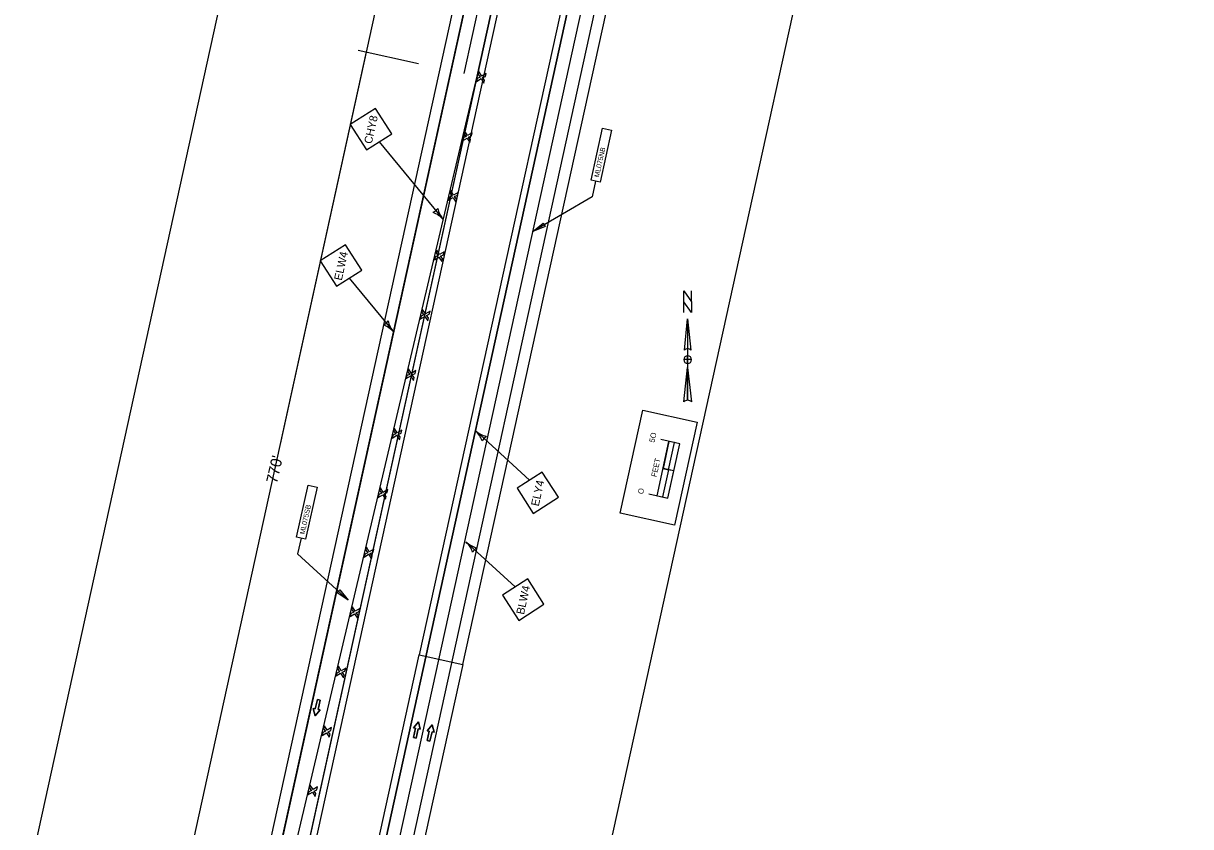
# Model space of a CAD drawing. Extents: x 14104283 to 14120882, y 8635219 to 8671666.
# Drawn here: x 14108027 to 14109077, y 8641619 to 8642342 of the extents above; entities that cross this region are included whole.
import ezdxf

# ---------------------------------------------------------------- set-up
doc = ezdxf.new("R2010")
doc.units = 0
for name, color, linetype in [('Cell', 7, 'Continuous'), ('dsnCellsNorthArrow', 7, 'Continuous'), ('dsnCellsScaleBlock', 7, 'Continuous'), ('dsnNonPlotable', 7, 'Continuous'), ('dsnPaintExistingEdgeLineRightWhite', 7, 'Continuous'), ('dsnPaintPlaceBrokenLineWhite', 7, 'Continuous'), ('dsnPaintPlaceEdgeLineLeftYellow', 7, 'Continuous'), ('dsnPaintPlaceEdgeLineRightWhite', 7, 'Continuous'), ('dsnPaintRemoveDoubleCenterLineYellow', 7, 'Continuous'), ('dsnShadingPaved', 7, 'Continuous'), ('dsnStdLabel', 7, 'Continuous'), ('dsnStgShadingPrevPav', 7, 'Continuous'), ('dsnTapePlaceChannelizingLaneYellow', 7, 'Continuous'), ('Text', 7, 'Continuous')]:
    doc.layers.add(name, color=color, linetype=linetype)

msp = doc.modelspace()

# ---------------------------------------------------------------- linework, layer by layer
at = {"layer": 'Cell'}
for p, q in [((14108436.6, 8642298.3), (14108435.9, 8642295.6)), ((14108439.1, 8642294.2), (14108436.6, 8642298.3)), ((14108443.1, 8642296.7), (14108439.1, 8642294.2)), ((14108442.5, 8642294), (14108443.1, 8642296.7)), ((14108435.1, 8642292.2), (14108434.5, 8642289.5)), ((14108434.5, 8642289.5), (14108438.5, 8642292)), ((14108437.7, 8642293.4), (14108435.1, 8642292.2)), ((14108435.9, 8642295.6), (14108437.7, 8642293.4)), ((14108438.5, 8642292), (14108441, 8642288)), ((14108439.9, 8642292.9), (14108442.5, 8642294)), ((14108441.7, 8642290.6), (14108439.9, 8642292.9)), ((14108441, 8642288), (14108441.7, 8642290.6)), ((14108423.9, 8642244.8), (14108423.3, 8642242.1)), ((14108426.4, 8642240.7), (14108423.9, 8642244.8)), ((14108422.5, 8642238.7), (14108421.8, 8642236)), ((14108421.8, 8642236), (14108425.9, 8642238.5)), ((14108425.1, 8642239.9), (14108422.5, 8642238.7)), ((14108423.3, 8642242.1), (14108425.1, 8642239.9)), ((14108425.9, 8642238.5), (14108428.4, 8642234.4)), ((14108430.5, 8642243.2), (14108426.4, 8642240.7)), ((14108427.3, 8642239.3), (14108429.9, 8642240.5)), ((14108429, 8642237.1), (14108427.3, 8642239.3)), ((14108428.4, 8642234.4), (14108429, 8642237.1)), ((14108429.9, 8642240.5), (14108430.5, 8642243.2)), ((14108411.3, 8642191.2), (14108410.7, 8642188.6)), ((14108413.8, 8642187.2), (14108411.3, 8642191.2)), ((14108409.8, 8642185.2), (14108409.2, 8642182.5)), ((14108409.2, 8642182.5), (14108413.3, 8642185)), ((14108412.4, 8642186.3), (14108409.8, 8642185.2)), ((14108410.7, 8642188.6), (14108412.4, 8642186.3)), ((14108413.3, 8642185), (14108415.7, 8642180.9)), ((14108417.9, 8642189.6), (14108413.8, 8642187.2)), ((14108414.6, 8642185.8), (14108417.2, 8642187)), ((14108416.4, 8642183.6), (14108414.6, 8642185.8)), ((14108415.7, 8642180.9), (14108416.4, 8642183.6)), ((14108417.2, 8642187), (14108417.9, 8642189.6)), ((14108397.2, 8642131.6), (14108396.5, 8642129)), ((14108396.5, 8642129), (14108400.6, 8642131.4)), ((14108399.8, 8642132.8), (14108397.2, 8642131.6)), ((14108398.7, 8642137.7), (14108398, 8642135)), ((14108398, 8642135), (14108399.8, 8642132.8)), ((14108401.2, 8642133.6), (14108398.7, 8642137.7)), ((14108400.6, 8642131.4), (14108403.1, 8642127.4)), ((14108405.2, 8642136.1), (14108401.2, 8642133.6)), ((14108402, 8642132.3), (14108404.6, 8642133.4)), ((14108403.8, 8642130), (14108402, 8642132.3)), ((14108403.1, 8642127.4), (14108403.8, 8642130)), ((14108404.6, 8642133.4), (14108405.2, 8642136.1)), ((14108384.6, 8642078.1), (14108383.9, 8642075.4)), ((14108383.9, 8642075.4), (14108388, 8642077.9)), ((14108387.2, 8642079.3), (14108384.6, 8642078.1)), ((14108386, 8642084.2), (14108385.4, 8642081.5)), ((14108385.4, 8642081.5), (14108387.2, 8642079.3)), ((14108388.5, 8642080.1), (14108386, 8642084.2)), ((14108388, 8642077.9), (14108390.5, 8642073.8)), ((14108392.6, 8642082.6), (14108388.5, 8642080.1)), ((14108389.3, 8642078.7), (14108391.9, 8642079.9)), ((14108391.1, 8642076.5), (14108389.3, 8642078.7)), ((14108390.5, 8642073.8), (14108391.1, 8642076.5)), ((14108391.9, 8642079.9), (14108392.6, 8642082.6)), ((14108371.9, 8642024.6), (14108371.3, 8642021.9)), ((14108371.3, 8642021.9), (14108375.4, 8642024.4)), ((14108374.5, 8642025.7), (14108371.9, 8642024.6)), ((14108373.4, 8642030.6), (14108372.7, 8642028)), ((14108372.7, 8642028), (14108374.5, 8642025.7)), ((14108375.9, 8642026.6), (14108373.4, 8642030.6)), ((14108375.4, 8642024.4), (14108377.8, 8642020.3)), ((14108380, 8642029.1), (14108375.9, 8642026.6)), ((14108376.7, 8642025.2), (14108379.3, 8642026.4)), ((14108378.5, 8642023), (14108376.7, 8642025.2)), ((14108377.8, 8642020.3), (14108378.5, 8642023)), ((14108379.3, 8642026.4), (14108380, 8642029.1)), ((14108359.3, 8641971), (14108358.6, 8641968.4)), ((14108358.6, 8641968.4), (14108362.7, 8641970.9)), ((14108361.9, 8641972.2), (14108359.3, 8641971)), ((14108360.8, 8641977.1), (14108360.1, 8641974.4)), ((14108360.1, 8641974.4), (14108361.9, 8641972.2)), ((14108363.2, 8641973), (14108360.8, 8641977.1)), ((14108362.7, 8641970.9), (14108365.2, 8641966.8)), ((14108367.3, 8641975.5), (14108363.2, 8641973)), ((14108364.1, 8641971.7), (14108366.7, 8641972.9)), ((14108365.8, 8641969.5), (14108364.1, 8641971.7)), ((14108366.7, 8641972.9), (14108367.3, 8641975.5)), ((14108365.2, 8641966.8), (14108365.8, 8641969.5)), ((14108349.2, 8641918.7), (14108346.7, 8641917.5)), ((14108348.1, 8641923.6), (14108347.5, 8641920.9)), ((14108347.5, 8641920.9), (14108349.2, 8641918.7)), ((14108350.6, 8641919.5), (14108348.1, 8641923.6)), ((14108354.7, 8641922), (14108350.6, 8641919.5)), ((14108351.4, 8641918.2), (14108354, 8641919.3)), ((14108353.2, 8641915.9), (14108351.4, 8641918.2)), ((14108354, 8641919.3), (14108354.7, 8641922)), ((14108346.7, 8641917.5), (14108346, 8641914.8)), ((14108346, 8641914.8), (14108350.1, 8641917.3)), ((14108350.1, 8641917.3), (14108352.6, 8641913.3)), ((14108352.6, 8641913.3), (14108353.2, 8641915.9)), ((14108335.5, 8641870.1), (14108334.8, 8641867.4)), ((14108334.8, 8641867.4), (14108336.6, 8641865.2)), ((14108338, 8641866), (14108335.5, 8641870.1)), ((14108342, 8641868.5), (14108338, 8641866)), ((14108338.8, 8641864.6), (14108341.4, 8641865.8)), ((14108341.4, 8641865.8), (14108342, 8641868.5)), ((14108334, 8641864), (14108333.4, 8641861.3)), ((14108333.4, 8641861.3), (14108337.4, 8641863.8)), ((14108336.6, 8641865.2), (14108334, 8641864)), ((14108337.4, 8641863.8), (14108339.9, 8641859.7)), ((14108340.6, 8641862.4), (14108338.8, 8641864.6)), ((14108339.9, 8641859.7), (14108340.6, 8641862.4)), ((14108322.8, 8641816.5), (14108322.2, 8641813.9)), ((14108322.2, 8641813.9), (14108324, 8641811.6)), ((14108325.3, 8641812.5), (14108322.8, 8641816.5)), ((14108329.4, 8641814.9), (14108325.3, 8641812.5)), ((14108328.8, 8641812.3), (14108329.4, 8641814.9)), ((14108321.4, 8641810.5), (14108320.7, 8641807.8)), ((14108320.7, 8641807.8), (14108324.8, 8641810.3)), ((14108324, 8641811.6), (14108321.4, 8641810.5)), ((14108324.8, 8641810.3), (14108327.3, 8641806.2)), ((14108326.2, 8641811.1), (14108328.8, 8641812.3)), ((14108327.9, 8641808.9), (14108326.2, 8641811.1)), ((14108327.3, 8641806.2), (14108327.9, 8641808.9)), ((14108310.2, 8641763), (14108309.6, 8641760.3)), ((14108312.7, 8641758.9), (14108310.2, 8641763)), ((14108316.8, 8641761.4), (14108312.7, 8641758.9)), ((14108316.1, 8641758.7), (14108316.8, 8641761.4)), ((14108308.7, 8641756.9), (14108308.1, 8641754.3)), ((14108308.1, 8641754.3), (14108312.2, 8641756.7)), ((14108311.3, 8641758.1), (14108308.7, 8641756.9)), ((14108309.6, 8641760.3), (14108311.3, 8641758.1)), ((14108312.2, 8641756.7), (14108314.7, 8641752.7)), ((14108313.5, 8641757.6), (14108316.1, 8641758.7)), ((14108315.3, 8641755.3), (14108313.5, 8641757.6)), ((14108314.7, 8641752.7), (14108315.3, 8641755.3)), ((14108297.6, 8641709.5), (14108296.9, 8641706.8)), ((14108300.1, 8641705.4), (14108297.6, 8641709.5)), ((14108296.1, 8641703.4), (14108295.5, 8641700.7)), ((14108295.5, 8641700.7), (14108299.5, 8641703.2)), ((14108298.7, 8641704.6), (14108296.1, 8641703.4)), ((14108296.9, 8641706.8), (14108298.7, 8641704.6)), ((14108299.5, 8641703.2), (14108302, 8641699.1)), ((14108304.1, 8641707.9), (14108300.1, 8641705.4)), ((14108300.9, 8641704), (14108303.5, 8641705.2)), ((14108302.7, 8641701.8), (14108300.9, 8641704)), ((14108302, 8641699.1), (14108302.7, 8641701.8)), ((14108303.5, 8641705.2), (14108304.1, 8641707.9)), ((14108284.9, 8641655.9), (14108284.3, 8641653.3)), ((14108287.4, 8641651.9), (14108284.9, 8641655.9)), ((14108283.5, 8641649.9), (14108282.8, 8641647.2)), ((14108282.8, 8641647.2), (14108286.9, 8641649.7)), ((14108286.1, 8641651), (14108283.5, 8641649.9)), ((14108284.3, 8641653.3), (14108286.1, 8641651)), ((14108286.9, 8641649.7), (14108289.4, 8641645.6)), ((14108291.5, 8641654.4), (14108287.4, 8641651.9)), ((14108288.3, 8641650.5), (14108290.9, 8641651.7)), ((14108290, 8641648.3), (14108288.3, 8641650.5)), ((14108289.4, 8641645.6), (14108290, 8641648.3)), ((14108290.9, 8641651.7), (14108291.5, 8641654.4))]:
    msp.add_line(p, q, dxfattribs=at)
for points in [[(14108291.3, 8641733.2), (14108293.7, 8641732.6), (14108291.9, 8641724.1), (14108293.7, 8641723.7), (14108289.3, 8641718.3), (14108287.6, 8641725), (14108289.4, 8641724.6)], [(14108380.2, 8641698.2), (14108377.7, 8641698.8), (14108379.6, 8641707.3), (14108377.8, 8641707.7), (14108382.2, 8641713.1), (14108383.9, 8641706.4), (14108382.1, 8641706.8)], [(14108392.5, 8641695.5), (14108390.1, 8641696.1), (14108391.9, 8641704.6), (14108390.1, 8641705), (14108394.5, 8641710.4), (14108396.2, 8641703.7), (14108394.4, 8641704.1)]]:
    msp.add_lwpolyline(points, close=True, dxfattribs=at)
for points in [[(14108289.4, 8641724.6), (14108287.6, 8641725), (14108289.3, 8641718.3), (14108293.7, 8641723.7), (14108291.9, 8641724.1), (14108293.7, 8641732.6), (14108291.3, 8641733.2), (14108289.4, 8641724.6)], [(14108382.1, 8641706.8), (14108383.9, 8641706.4), (14108382.2, 8641713.1), (14108377.8, 8641707.7), (14108379.6, 8641707.3), (14108377.7, 8641698.8), (14108380.2, 8641698.2), (14108382.1, 8641706.8)], [(14108394.4, 8641704.1), (14108396.2, 8641703.7), (14108394.5, 8641710.4), (14108390.1, 8641705), (14108391.9, 8641704.6), (14108390.1, 8641696.1), (14108392.5, 8641695.5), (14108394.4, 8641704.1)]]:
    msp.add_lwpolyline(points, dxfattribs=at)
at = {"layer": 'dsnCellsNorthArrow'}
for p, q in [((14108624.4, 8642075.6), (14108627.2, 8642047.4)), ((14108624.4, 8642075.6), (14108624.4, 8642002.4)), ((14108621.6, 8642047.4), (14108621.6, 8642047.4)), ((14108621.7, 8642047.7), (14108622.2, 8642048.3)), ((14108624.4, 8642035.5), (14108624.4, 8642035.5)), ((14108620.9, 8642001), (14108624.4, 8642032))]:
    msp.add_line(p, q, dxfattribs=at)
msp.add_lwpolyline([(14108627.9, 8642081.3), (14108620.9, 8642091.1), (14108620.9, 8642101), (14108627.9, 8642091.1)], close=True, dxfattribs=at)
for points in [[(14108620.9, 8642081.3), (14108620.9, 8642101), (14108627.9, 8642091.1), (14108627.9, 8642101)], [(14108621.6, 8642047.4), (14108624.4, 8642075.6), (14108624.4, 8642048.9)], [(14108624.4, 8642035.5), (14108624.4, 8642039), (14108620.9, 8642039)], [(14108627.9, 8642039), (14108624.4, 8642039), (14108624.4, 8642042.5)], [(14108624.4, 8642002.4), (14108624.4, 8642032), (14108627.9, 8642001)]]:
    msp.add_lwpolyline(points, dxfattribs=at)
for centre, radius, start, end in [((14108624.4, 8642045.3), 3.52, 90.0204, 143.1257), ((14108624.4, 8642045.3), 3.52, 36.8481, 90.0218), ((14108624.4, 8642039), 3.52, 90, 180), ((14108624.4, 8642039), 3.52, 180, 270), ((14108624.4, 8642039), 3.52, 0, 90), ((14108624.4, 8642039), 3.52, 270, 360), ((14108624.4, 8641997.3), 5.1, 89.9894, 133.619), ((14108624.4, 8641997.3), 5.11, 46.4021, 90.0006)]:
    msp.add_arc(centre, radius, start, end, dxfattribs=at)
at = {"layer": 'dsnCellsScaleBlock'}
msp.add_line((14108612, 8641938.8), (14108602.3, 8641940.9), dxfattribs=at)
msp.add_line((14108612, 8641938.8), (14108602.3, 8641940.9), dxfattribs=at)
for points in [[(14108612.6, 8641890), (14108563.8, 8641900.8), (14108584.1, 8641993.6), (14108633, 8641982.8)], [(14108563.8, 8641900.8), (14108584.1, 8641993.6), (14108633, 8641982.8), (14108612.6, 8641890)], [(14108612.6, 8641890), (14108563.8, 8641900.8), (14108584.1, 8641993.6), (14108633, 8641982.8)], [(14108607.1, 8641939.9), (14108612.5, 8641964.3), (14108607.6, 8641965.4), (14108602.3, 8641940.9)], [(14108606.7, 8641914.4), (14108612, 8641938.8), (14108607.1, 8641939.9), (14108601.8, 8641915.5)]]:
    msp.add_lwpolyline(points, close=True, dxfattribs=at)
for points in [[(14108589.6, 8641918.1), (14108606.7, 8641914.4), (14108617.4, 8641963.2), (14108600.3, 8641967)], [(14108596.9, 8641916.5), (14108607.6, 8641965.4)]]:
    msp.add_lwpolyline(points, dxfattribs=at)
at = {"layer": 'dsnNonPlotable'}
msp.add_lwpolyline([(14107966.2, 8641278.2), (14108302.6, 8642809.2), (14108795.9, 8642700.9), (14108459.5, 8641169.9)], close=True, dxfattribs=at)
at = {"layer": 'dsnPaintExistingEdgeLineRightWhite'}
msp.add_line((14108201.6, 8640807.6), (14108724, 8643185.7), dxfattribs=at)
at = {"layer": 'dsnPaintPlaceBrokenLineWhite'}
msp.add_line((14108423.2, 8642296.7), (14108623.3, 8643207.7), dxfattribs=at)
msp.add_lwpolyline([(14108306.4, 8641340.7), (14108389, 8641717), (14108712.3, 8643188.3), (14108894.6, 8644035.3), (14109077, 8644882.2)], dxfattribs=at)
at = {"layer": 'dsnPaintPlaceEdgeLineLeftYellow'}
msp.add_line((14108199.6, 8640910.3), (14108700.5, 8643190.8), dxfattribs=at)
msp.add_lwpolyline([(14108999.8, 8644898.8), (14108635.1, 8643205.1), (14108434.9, 8642294.1)], dxfattribs=at)
at = {"layer": 'dsnPaintPlaceEdgeLineRightWhite'}
msp.add_lwpolyline([(14108976.3, 8644903.9), (14108611.6, 8643210.2), (14108202.1, 8641346.1)], dxfattribs=at)
at = {"layer": 'dsnPaintRemoveDoubleCenterLineYellow'}
msp.add_lwpolyline([(14108306.4, 8641340.7), (14108389, 8641717), (14108712.3, 8643188.3), (14108894.6, 8644035.3), (14109077, 8644882.2)], dxfattribs=at)
at = {"layer": 'dsnShadingPaved'}
for p, q in [((14108700.5, 8643190.9), (14108199.6, 8640910.3)), ((14108201.6, 8640807.6), (14108724, 8643185.7)), ((14108258, 8641544.6), (14108434.9, 8642294.1))]:
    msp.add_line(p, q, dxfattribs=at)
for points in [[(14108976.3, 8644903.9), (14108611.6, 8643210.2), (14108202.1, 8641346.1)], [(14108434.9, 8642294.1), (14108635.1, 8643205.1), (14108999.8, 8644898.8)]]:
    msp.add_lwpolyline(points, dxfattribs=at)
at = {"layer": 'dsnStdLabel'}
for p, q in [((14108438.7, 8642786.8), (14108257.8, 8641963)), ((14108328.1, 8642317.6), (14108382.2, 8642305.7)), ((14108335.3, 8642316), (14108170.1, 8641563.9)), ((14108346.8, 8642235.1), (14108404.5, 8642165.2)), ((14108319.8, 8642112.4), (14108359.8, 8642063.9)), ((14108482.2, 8641930.5), (14108433.5, 8641975.1)), ((14108469.2, 8641834.4), (14108424.9, 8641874.9))]:
    msp.add_line(p, q, dxfattribs=at)
for points in [[(14108335.4, 8642227.8), (14108358.2, 8642242.4), (14108343.6, 8642265.1), (14108320.9, 8642250.6)], [(14108308.5, 8642105.1), (14108331.2, 8642119.7), (14108316.6, 8642142.4), (14108293.9, 8642127.9)], [(14108485.4, 8641900.5), (14108508.1, 8641915.1), (14108493.6, 8641937.8), (14108470.9, 8641923.3)], [(14108472.4, 8641804.3), (14108495.1, 8641818.9), (14108480.6, 8641841.6), (14108457.9, 8641827.1)]]:
    msp.add_lwpolyline(points, close=True, dxfattribs=at)
for centre, radius, start, end in [((14108392, 8642179.8), 8.86, 292.8385, 328.307), ((14108387.1, 8642150.2), 22.9, 40.5727, 68.6439), ((14108421.9, 8642180.1), 22.9, 192.5015, 220.5728), ((14108347.3, 8642078.6), 8.86, 292.8385, 328.307), ((14108342.4, 8642049), 22.9, 40.5727, 68.6439), ((14108377.2, 8642078.9), 22.9, 192.5015, 220.5728), ((14108418, 8641958.2), 22.9, 19.4977, 47.569), ((14108448.9, 8641992.1), 22.9, 227.5689, 255.6401), ((14108447.7, 8641962.1), 8.86, 119.8347, 155.3031), ((14108409.4, 8641858), 22.9, 19.4977, 47.569), ((14108440.4, 8641891.8), 22.9, 227.5689, 255.6401), ((14108439.1, 8641861.9), 8.86, 119.8347, 155.3031)]:
    msp.add_arc(centre, radius, start, end, dxfattribs=at)
at = {"layer": 'dsnStgShadingPrevPav'}
for p, q in [((14108107.8, 8640963.3), (14108601.8, 8643212.3)), ((14108611.6, 8643210.2), (14108117.6, 8640961.2)), ((14108694.7, 8643192.1), (14108383, 8641773.2)), ((14108422, 8641764.6), (14108733.8, 8643183.6)), ((14108383, 8641773.2), (14108422, 8641764.6))]:
    msp.add_line(p, q, dxfattribs=at)
for points in [[(14108202.1, 8641346.1), (14108611.6, 8643210.2), (14108976.3, 8644903.9)], [(14108999.8, 8644898.8), (14108817.4, 8644052), (14108635.1, 8643205.1), (14108387.9, 8642080.1), (14108140.8, 8640955.1)], [(14108146.7, 8640953.8), (14108640.9, 8643203.9), (14109005.6, 8644897.6)], [(14108999.8, 8644898.8), (14108635.1, 8643205.1), (14108225.5, 8641340.9)]]:
    msp.add_lwpolyline(points, dxfattribs=at)
msp.add_lwpolyline([(14108081.5, 8640400.9), (14108123.3, 8640591.3), (14108126.6, 8640606), (14108216.7, 8641016.2), (14108268.2, 8641250.6), (14108383, 8641773.2), (14108422, 8641764.6), (14108309.4, 8641251.8), (14108270.2, 8641073.5), (14108265.9, 8641054), (14108255.7, 8641007.6), (14108202.1, 8640763.4), (14108120.6, 8640392.3)], close=True, dxfattribs=at)
at = {"layer": 'dsnTapePlaceChannelizingLaneYellow'}
msp.add_line((14108258, 8641544.6), (14108434.9, 8642294.1), dxfattribs=at)
at = {"layer": 'Text'}
for points in [[(14108537.5, 8642200.5), (14108547.8, 8642247.5), (14108556, 8642245.7), (14108545.7, 8642198.7)], [(14108537.5, 8642200.5), (14108547.8, 8642247.5), (14108556, 8642245.7), (14108545.7, 8642198.7)], [(14108485.1, 8642154.4), (14108494.4, 8642161.9), (14108496.2, 8642158.8)], [(14108272.5, 8641879.1), (14108282.9, 8641926.1), (14108291.1, 8641924.2), (14108280.7, 8641877.3)], [(14108272.5, 8641879.1), (14108282.9, 8641926.1), (14108291.1, 8641924.2), (14108280.7, 8641877.3)], [(14108319.1, 8641822.5), (14108309.1, 8641829.2), (14108311.5, 8641831.8)]]:
    msp.add_lwpolyline(points, close=True, dxfattribs=at)
for points in [[(14108541.6, 8642199.6), (14108538.4, 8642185.6), (14108485.1, 8642154.4)], [(14108276.6, 8641878.2), (14108273.5, 8641864.2), (14108319.1, 8641822.5)]]:
    msp.add_lwpolyline(points, dxfattribs=at)

# ---------------------------------------------------------------- texts
at = {"layer": 'dsnCellsScaleBlock'}
for s, p in [('5O', (14108594.6, 8641964.1)), ('FEET', (14108596.4, 8641933)), ('O', (14108584.3, 8641917.6))]:
    msp.add_text(s, height=5, rotation=77.6078, dxfattribs=at).set_placement(p)
at = {"layer": 'dsnStdLabel'}
for s, height, rotation, p in [('CHY8', 7.2, 77.6078, (14108340.2, 8642232.8)), ('ELW4', 7.2, 77.6078, (14108313.2, 8642109.8)), ("770'", 10, 77.0531, (14108254.8, 8641927)), ('ELY4', 7.2, 77.6078, (14108490.4, 8641906.6)), ('BLW4', 7.2, 77.6078, (14108477.1, 8641809.1))]:
    msp.add_text(s, height=height, rotation=rotation, dxfattribs=at).set_placement(p)
at = {"layer": 'Text'}
for s, p in [('ML075NB', (14108544.6, 8642202.8)), ('ML075SB', (14108279.7, 8641881.4))]:
    msp.add_text(s, height=4.48, rotation=77.6078, dxfattribs=at).set_placement(p)

doc.saveas('drawing.dxf')
